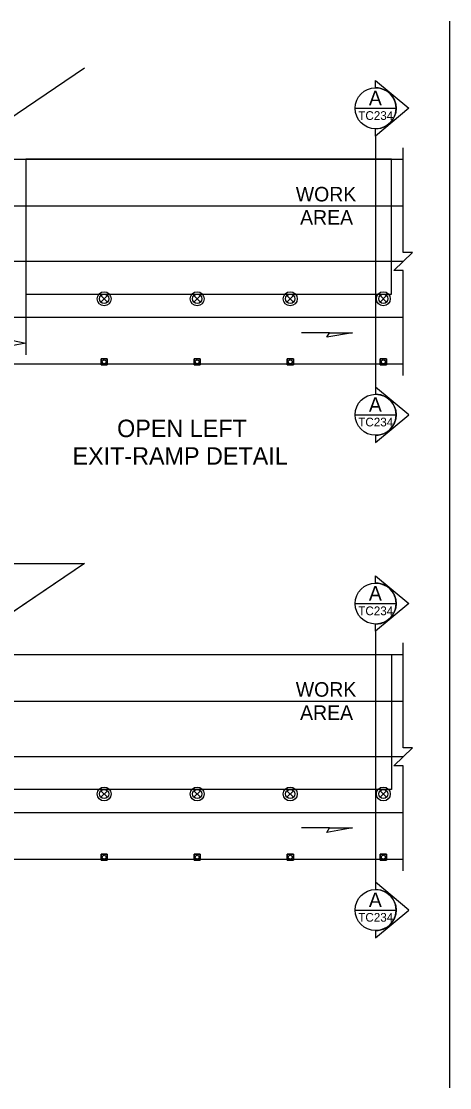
# Model space of a CAD drawing. Extents: x 99999 to 100116, y 99995 to 100013.
# Drawn here: x 100064.93 to 100067.88, y 100001.58 to 100008.92 of the extents above; entities that cross this region are included whole.
import ezdxf

# ---------------------------------------------------------------- set-up
doc = ezdxf.new("R2010")
doc.units = 0
for name, color, linetype in [('RD_MK_LineEdgeYellow', 7, 'Continuous'), ('RD_MK_LineLane', 7, 'Continuous'), ('SH_DE_DetailHeading2Text', 7, 'Continuous'), ('SH_TI_WZSectionCut', 7, 'Continuous'), ('TR_WZ_TrafficCone', 7, 'Continuous'), ('TR_WZ_TrafficSafetyDrum', 7, 'Continuous'), ('TR_WZ_WorkAreaLabel', 7, 'Continuous'), ('TR_WZ_WorkZoneDetails', 7, 'Continuous')]:
    doc.layers.add(name, color=color, linetype=linetype)

msp = doc.modelspace()

# ---------------------------------------------------------------- linework, layer by layer
at = {"layer": 'RD_MK_LineEdgeYellow'}
for p, q in [((100064.4388, 100007.648), (100067.555, 100007.648)), ((100060.32, 100006.88), (100067.555, 100006.88)), ((100064.4388, 100004.238), (100067.555, 100004.238)), ((100060.32, 100003.47), (100067.555, 100003.47))]:
    msp.add_line(p, q, dxfattribs=at)
at = {"layer": 'RD_MK_LineLane'}
for points in [[(100067.555, 100007.264), (100060.32, 100007.264)], [(100067.555, 100003.854), (100060.32, 100003.854)]]:
    msp.add_lwpolyline(points, dxfattribs=at)
at = {"layer": 'SH_TI_WZSectionCut'}
for p, q in [((100067.3657, 100008.4604), (100067.3657, 100008.5103)), ((100067.3657, 100008.5103), (100067.5938, 100008.3192)), ((100067.5938, 100008.3192), (100067.3657, 100008.128)), ((100067.3657, 100008.128), (100067.3657, 100008.1779)), ((100067.3657, 100008.128), (100067.3657, 100006.4)), ((100067.3657, 100006.4), (100067.3657, 100006.3501)), ((100067.5939, 100006.2089), (100067.3657, 100006.4)), ((100067.3657, 100006.0178), (100067.5939, 100006.2089)), ((100067.3657, 100006.0677), (100067.3657, 100006.0178)), ((100067.3657, 100005.0503), (100067.3657, 100005.1002)), ((100067.3657, 100005.1002), (100067.5938, 100004.9091)), ((100067.5938, 100004.9091), (100067.3657, 100004.718)), ((100067.3657, 100004.718), (100067.3657, 100004.7679)), ((100067.3657, 100004.718), (100067.3657, 100002.99)), ((100067.3657, 100002.99), (100067.3657, 100002.94)), ((100067.5939, 100002.7988), (100067.3657, 100002.99)), ((100067.3657, 100002.6077), (100067.5939, 100002.7988)), ((100067.3657, 100002.6576), (100067.3657, 100002.6077))]:
    msp.add_line(p, q, dxfattribs=at)
for points in [[(100067.2245, 100008.3192), (100067.5069, 100008.3192)], [(100067.2245, 100006.2089), (100067.5069, 100006.2089)], [(100067.2245, 100004.9091), (100067.5069, 100004.9091)], [(100067.2245, 100002.7988), (100067.5069, 100002.7988)]]:
    msp.add_lwpolyline(points, dxfattribs=at)
for centre in [(100067.3657, 100008.3192), (100067.3657, 100006.2089), (100067.3657, 100004.9091), (100067.3657, 100002.7988)]:
    msp.add_circle(centre, 0.1412, dxfattribs=at)
for centre in [(100067.3657, 100008.3192), (100067.3657, 100006.2089), (100067.3657, 100004.9091), (100067.3657, 100002.7988)]:
    msp.add_arc(centre, 0.1412, 269.99779, 90.00221, dxfattribs=at)
at = {"layer": 'TR_WZ_TrafficCone'}
for points in [[(100065.4776, 100006.552), (100065.5203, 100006.552), (100065.5203, 100006.5947), (100065.4776, 100006.5947), (100065.4776, 100006.552)], [(100065.4776, 100006.5947), (100065.5203, 100006.5947), (100065.5203, 100006.552), (100065.4776, 100006.552), (100065.4776, 100006.5947)], [(100066.1176, 100006.552), (100066.1603, 100006.552), (100066.1603, 100006.5947), (100066.1176, 100006.5947), (100066.1176, 100006.552)], [(100066.1176, 100006.5947), (100066.1603, 100006.5947), (100066.1603, 100006.552), (100066.1176, 100006.552), (100066.1176, 100006.5947)], [(100066.7576, 100006.552), (100066.8003, 100006.552), (100066.8003, 100006.5947), (100066.7576, 100006.5947), (100066.7576, 100006.552)], [(100066.7576, 100006.5947), (100066.8003, 100006.5947), (100066.8003, 100006.552), (100066.7576, 100006.552), (100066.7576, 100006.5947)], [(100067.3976, 100006.552), (100067.4403, 100006.552), (100067.4403, 100006.5947), (100067.3976, 100006.5947), (100067.3976, 100006.552)], [(100067.3976, 100006.5947), (100067.4403, 100006.5947), (100067.4403, 100006.552), (100067.3976, 100006.552), (100067.3976, 100006.5947)], [(100065.4776, 100003.142), (100065.5203, 100003.142), (100065.5203, 100003.1846), (100065.4776, 100003.1846), (100065.4776, 100003.142)], [(100065.4776, 100003.1846), (100065.5203, 100003.1846), (100065.5203, 100003.142), (100065.4776, 100003.142), (100065.4776, 100003.1846)], [(100066.1176, 100003.142), (100066.1603, 100003.142), (100066.1603, 100003.1846), (100066.1176, 100003.1846), (100066.1176, 100003.142)], [(100066.1176, 100003.1846), (100066.1603, 100003.1846), (100066.1603, 100003.142), (100066.1176, 100003.142), (100066.1176, 100003.1846)], [(100066.7576, 100003.142), (100066.8003, 100003.142), (100066.8003, 100003.1846), (100066.7576, 100003.1846), (100066.7576, 100003.142)], [(100066.7576, 100003.1846), (100066.8003, 100003.1846), (100066.8003, 100003.142), (100066.7576, 100003.142), (100066.7576, 100003.1846)], [(100067.3976, 100003.142), (100067.4403, 100003.142), (100067.4403, 100003.1846), (100067.3976, 100003.1846), (100067.3976, 100003.142)], [(100067.3976, 100003.1846), (100067.4403, 100003.1846), (100067.4403, 100003.142), (100067.3976, 100003.142), (100067.3976, 100003.1846)]]:
    msp.add_lwpolyline(points, dxfattribs=at)
for centre in [(100065.4989, 100006.5734), (100066.1389, 100006.5734), (100066.7789, 100006.5734), (100067.4189, 100006.5734), (100065.4989, 100003.1633), (100066.1389, 100003.1633), (100066.7789, 100003.1633), (100067.4189, 100003.1633)]:
    msp.add_circle(centre, 0.0133, dxfattribs=at)
at = {"layer": 'TR_WZ_TrafficSafetyDrum'}
for p, q in [((100065.4763, 100006.9854), (100065.5215, 100007.0306)), ((100065.5215, 100006.9854), (100065.4763, 100007.0306)), ((100066.1163, 100006.9854), (100066.1615, 100007.0306)), ((100066.1615, 100006.9854), (100066.1163, 100007.0306)), ((100066.7563, 100006.9854), (100066.8015, 100007.0306)), ((100066.8015, 100006.9854), (100066.7563, 100007.0306)), ((100067.3963, 100006.9854), (100067.4415, 100007.0306)), ((100067.4415, 100006.9854), (100067.3963, 100007.0306)), ((100065.4763, 100003.5753), (100065.5215, 100003.6206)), ((100065.5215, 100003.5753), (100065.4763, 100003.6206)), ((100066.1163, 100003.5753), (100066.1615, 100003.6206)), ((100066.1615, 100003.5753), (100066.1163, 100003.6206)), ((100066.7563, 100003.5753), (100066.8015, 100003.6206)), ((100066.8015, 100003.5753), (100066.7563, 100003.6206)), ((100067.3963, 100003.5753), (100067.4415, 100003.6206)), ((100067.4415, 100003.5753), (100067.3963, 100003.6206))]:
    msp.add_line(p, q, dxfattribs=at)
for centre, radius in [((100065.4989, 100007.008), 0.048), ((100065.4989, 100007.008), 0.048), ((100065.4989, 100007.008), 0.032), ((100066.1389, 100007.008), 0.048), ((100066.1389, 100007.008), 0.048), ((100066.1389, 100007.008), 0.032), ((100066.7789, 100007.008), 0.048), ((100066.7789, 100007.008), 0.048), ((100066.7789, 100007.008), 0.032), ((100067.4189, 100007.008), 0.048), ((100067.4189, 100007.008), 0.048), ((100067.4189, 100007.008), 0.032), ((100065.4989, 100003.598), 0.048), ((100065.4989, 100003.598), 0.048), ((100065.4989, 100003.598), 0.032), ((100066.1389, 100003.598), 0.048), ((100066.1389, 100003.598), 0.048), ((100066.1389, 100003.598), 0.032), ((100066.7789, 100003.598), 0.048), ((100066.7789, 100003.598), 0.048), ((100066.7789, 100003.598), 0.032), ((100067.4189, 100003.598), 0.048), ((100067.4189, 100003.598), 0.048), ((100067.4189, 100003.598), 0.032)]:
    msp.add_circle(centre, radius, dxfattribs=at)
at = {"layer": 'TR_WZ_WorkZoneDetails'}
for p, q in [((100067.875, 100008.9181), (100067.875, 100001.5759)), ((100065.3633, 100008.595), (100064.4388, 100007.968)), ((100064.4388, 100007.968), (100067.555, 100007.968)), ((100064.9608, 100007.04), (100064.9608, 100006.6217)), ((100067.0492, 100006.7739), (100066.8563, 100006.7739)), ((100060.32, 100006.56), (100067.555, 100006.56)), ((100065.3633, 100005.1849), (100064.4388, 100004.558)), ((100064.4388, 100004.558), (100067.555, 100004.558)), ((100067.0492, 100003.3639), (100066.8563, 100003.3639)), ((100060.32, 100003.15), (100067.555, 100003.15))]:
    msp.add_line(p, q, dxfattribs=at)
for points in [[(100067.555, 100006.48), (100067.555, 100007.2021), (100067.491, 100007.2021), (100067.619, 100007.326), (100067.555, 100007.326), (100067.555, 100008.048)], [(100067.555, 100003.07), (100067.555, 100003.792), (100067.491, 100003.792), (100067.619, 100003.9159), (100067.555, 100003.9159), (100067.555, 100004.638)]]:
    msp.add_lwpolyline(points, dxfattribs=at)
for points in [[(100064.9608, 100007.968), (100064.9608, 100007.04), (100067.475, 100007.04), (100067.475, 100007.968)], [(100067.2065, 100006.7739), (100067.0314, 100006.7431), (100067.0492, 100006.7739)], [(100064.9608, 100006.7031), (100064.8625, 100006.6838), (100064.867, 100006.7031), (100064.8625, 100006.7224)], [(100060.4, 100004.558), (100062.9559, 100004.558), (100063.8809, 100005.1849), (100065.3633, 100005.1849), (100064.4388, 100004.558), (100065.8504, 100004.558), (100067.475, 100004.558), (100067.475, 100003.63), (100060.4, 100003.63)], [(100067.2065, 100003.3639), (100067.0314, 100003.333), (100067.0492, 100003.3639)]]:
    msp.add_lwpolyline(points, close=True, dxfattribs=at)

# ---------------------------------------------------------------- texts
at = {"layer": 'SH_DE_DetailHeading2Text'}
for s, p in [('OPEN LEFT', (100065.5881, 100006.0554)), ('EXIT-RAMP DETAIL', (100065.2814, 100005.8654))]:
    msp.add_text(s, height=0.12, rotation=360, dxfattribs=at).set_placement(p)
at = {"layer": 'SH_TI_WZSectionCut'}
for s, height, rotation, p in [('A', 0.1, 0.00995, (100067.3195, 100008.3398)), ('TC234', 0.06, 360, (100067.2464, 100008.2392)), ('A', 0.1, 0.00995, (100067.3195, 100006.2295)), ('TC234', 0.06, 360, (100067.2464, 100006.1289)), ('A', 0.1, 0.00995, (100067.3195, 100004.9297)), ('TC234', 0.06, 360, (100067.2464, 100004.8291)), ('A', 0.1, 0.00995, (100067.3195, 100002.8195)), ('TC234', 0.06, 360, (100067.2464, 100002.7188))]:
    msp.add_text(s, height=height, rotation=rotation, dxfattribs=at).set_placement(p)
at = {"layer": 'TR_WZ_WorkAreaLabel'}
for s, p in [('WORK', (100066.8169, 100007.678)), ('AREA', (100066.8465, 100007.518)), ('WORK', (100066.8169, 100004.268)), ('AREA', (100066.8465, 100004.108))]:
    msp.add_text(s, height=0.1, dxfattribs=at).set_placement(p)

doc.saveas('drawing.dxf')
